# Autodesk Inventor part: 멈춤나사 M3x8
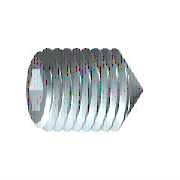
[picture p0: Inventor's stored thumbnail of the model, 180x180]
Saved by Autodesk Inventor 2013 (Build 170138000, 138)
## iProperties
Created: 2012-02
Part Number: 멈춤나사 M3x8
Material: 강철, 연강
Description: 6각 소켓 머리 없는 멈춤 나사
Document SubType Name: Modeling
Standard: KS B 1028
Designer: mduedu
Standards Organization: KS
Language: ko-KR
Size Designation: 원추점 M3x8
Categories: <MemberInstance><Categories><Category DisplayName="조임쇠" InternalName="e4da775c-781d-43d5-af7c-5136215cf5a6" Mnemonic="FSTN"><Category DisplayName="볼트" InternalN
Density: 7.86 g/cm^3
Mass: 0.360339 g
Surface Area: 0.888172 cm^2
Volume: 0.0458447 cm^3
IsCustomPart: 1
Author: mduedu
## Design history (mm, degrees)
sketch "스케치1"
  geometry: L1 (0, 0)-(5.5, 0); L2 (8, 0.866)-(8, 1.5); L3 (8, 1.5)-(0, 1.5); L4 (8, 0.866)-(6, 0.866); L5 (6, 0.866)-(5.5, 0); L6 (0, -0.3)-(0, 1.8) reference; L7 (0, 1.5)-(0, 0)
  constraints: 13 end point, 3 parallel, 1 collinear, 1 perpendicular, 1 point on line
  dimensions: "d0" = 2 distance of L2.start L4.end (= INTI); "d1" = 60 deg angle of L5 L1; "d2" = 3 diameter of L3 L1 (= NND); "d3" = 1.73205 diameter of L4 L1 (= 1.1547 x SW); "d5" = 8 distance from line of L2 L3.end (= NLG)
revolve "본체" sketch "스케치1" stored, may be unused: angle "d6" = 90 deg
sketch "스케치2"
  geometry: L1 (-0.433, 0.75)-(0.433, 0.75); L2 (0.433, 0.75)-(0.866, 0); L3 (0.866, 0)-(0.433, -0.75); L4 (0.433, -0.75)-(-0.433, -0.75); L5 (-0.433, -0.75)-(-0.866, 0); L6 (-0.866, 0)-(-0.433, 0.75); 3 further points
  constraints: 12 end point, 1 coincident, 1 horizontal, 13 other
extrude "슬롯" join sketch "스케치2" taper "d7" = 0 deg; stored distance "d21" = 10
workaxis "Work Axis1"
workplane "Work Plane1"
sketch "스케치5"
  geometry: L1 (-4, -0.15)-(-2.65, -1.5) reference; L2 (-4, 0.15)-(-2.65, 1.5) reference; L3 (-2.65, 1.5)-(-4.15, 0); L4 (-2.65, -1.5)-(-4.15, 0); 1 further point
  constraints: 4 end point, 1 horizontal alignment, 1 perpendicular
node "작업점1"
body "Solid1"
feature "스레드" dims "d12" = 8 (= NLG), "d13" = 0
chamfer "모따기1" distance "d8" = 1.35 (computed from NND, SPD, FAWI); stored, may be unused: angle "d9" = 45 deg (= FAWI), second distance "d34" = 1.35 (computed from NND, SPD, FAWI)
chamfer "모따기2" distance "d10" = 0.30673 (= -0.5 x GD1 + 0.5 x NND); stored, may be unused: angle "d11" = 45 deg (= FAWI), second distance "d35" = 0.30673 (= -0.5 x GD1 + 0.5 x NND)
other parameters: "NND" = 3 [user parameter; used in 5 equation terms], "NLG" = 8 [user parameter; used in 2 equation terms], "INTI" = 2 [user parameter; used in 1 equation term], "FAWI" = 45 deg [user parameter; used in 4 equation terms], "SW" = 1.5 [user parameter; used in 2 equation terms], "GD1" = 2.38655 (= THREADDIA - 1.2269 x PTC) [user parameter; used in 2 equation terms], "d4" = 0, "FAWI1" = 45 deg [user parameter], "SPD" = 0.3 [user parameter; used in 2 equation terms], "d36" = 0, "d37" = 0, "GUL" = 0.30673 (= 0.61345 x PTC) [user parameter], "TOA" = 30 deg [user parameter], "THREADDIA" = 3 [user parameter; used in 1 equation term], "PTC" = 0.5 [user parameter; used in 4 equation terms], "GAL" = 0.30673 (= 0.61345 x PTC) [user parameter], "E0" = 1.7325 (= 1.155 x SW) [user parameter]
